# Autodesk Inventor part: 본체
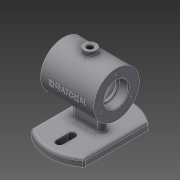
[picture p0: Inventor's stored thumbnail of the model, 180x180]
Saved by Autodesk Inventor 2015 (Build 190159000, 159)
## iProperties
Created: 2017-12
Part Number: 본체
Material: 일반
Document SubType Name: Modeling
Designer: SCD-A05
Density: 1 g/cm^3
Appearance: 기본값
Author: SCD-A05
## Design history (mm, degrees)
sketch "스케치1"
  geometry: L1 (-35, -42.426)-(-35, 42.426); L2 (35, 42.426)-(35, -42.426); A1 r 55 centre (0, 0) between (35, 42.426) and (-35, 42.426); A2 r 55 centre (0, 0) between (-35, -42.426) and (35, -42.426); 1 further point
  constraints: 4 end point, 4 point on circle, 2 centre point, 1 coincident, 1 parallel, 1 vertical
  dimensions: "d1" = 70 distance between parallel lines of L1 L2; "d2" = 35 distance from line of point (0, 0) L1; "d3" = 55 radius of A1; "d4" = 55 radius of A2
extrude "돌출1" new body sketch "스케치1" distance "d5" = 10; taper "d6" = 0 deg
sketch "스케치2"
  geometry: L1 (-15, -5)-(15, -5); L2 (15, 5)-(-15, 5); A1 r 55 centre (0, 0) between (-35, -42.426) and (35, -42.426) reference; A2 r 5 centre (-15, 0) between (-15, 5) and (-20, 0); A3 r 5 centre (-15, 0) between (-20, 0) and (-15, -5); A4 r 5 centre (15, 0) between (20, 0) and (15, 5); A5 r 5 centre (15, 0) between (15, -5) and (20, 0); 2 further points
  constraints: 8 point on circle, 4 centre point, 4 end point, 4 tangent, 2 concentric, 2 horizontal, 2 point on line, 1 parallel, 12 other
  dimensions: "d9" = 5 radius of A2; "d10" = 5 radius of A4; "d11" = 30 distance of A2.centre A4.centre; "d13" = 15 distance of A2.centre A1.centre; "d14" = 0 vertical distance of A1.centre A5.centre; "d15" = 10 distance between parallel lines of L2 L1
extrude "돌출2" join sketch "스케치2" distance "d16" = 52; taper "d17" = 0 deg
node "작업 평면1"
sketch "스케치5"
  geometry: L1 (-20, -10)-(-20, 0) reference; L2 (-20, 0)-(-5, 0) reference; L3 (-5, 0)-(-5, 52) reference; L4 (-5, 52)-(35, 52) reference; L5 (35, 52)-(35, 0) reference; L6 (35, 0)-(50, 0) reference; L7 (50, 0)-(50, -10) reference; L8 (50, -10)-(-20, -10) reference; L9 (-20, 82)-(50, 82); L10 (50, 82)-(50, 52); L11 (-20, 82)-(-20, 52); L12 (-20, 52)-(-5, 52); L13 (35, 52)-(50, 52); 1 further point
  constraints: 11 end point, 2 horizontal, 2 vertical, 1 collinear, 1 perpendicular
  dimensions: "d18" = 70 distance of L9.start L9.end; "d19" = 30 distance of L9.end L10.end; "d20" = 35 distance from line of point (15, -10) L11
revolve "회전1" sketch "스케치5" stored, may be unused: angle "d21" = 90 deg
sketch "스케치6"
  geometry: C1 r 30 at (0, 0) reference; C2 r 16 at (0, 0); 1 further point
  constraints: 1 centre point, 1 coincident
  dimensions: "d22" = 32 diameter of C2
extrude "돌출3" cut sketch "스케치6" distance "d23" = 12; taper "d24" = 0 deg
sketch "스케치7"
  geometry: C1 r 30 at (0, 0) reference; C2 r 16 at (0, 0); 1 further point
  constraints: 1 centre point, 1 coincident
  dimensions: "d25" = 32 diameter of C2
extrude "돌출4" cut sketch "스케치7" distance "d26" = 12; taper "d27" = 0 deg
node "작업 평면3"
sketch "스케치8"
  geometry: L1 (-52, -51.235)-(-62, -51.235) reference; L2 (-62, -51.235)-(-62, 51.235) reference; L3 (-62, 51.235)-(-52, 51.235) reference; L4 (-52, 51.235)-(-52, 0) reference; L5 (-52, 0)-(-52, -51.235) reference; L6 (-52, 0)-(-30, 0) reference; C1 r 25 at (0, 0); 2 further points
  constraints: 1 centre point, 1 coincident, 1 horizontal alignment
  dimensions: "d29" = 50 diameter of C1
extrude "돌출5" cut sketch "스케치8" distance "d30" = 40; taper "d31" = 0 deg
sketch "스케치9"
  geometry: C1 r 16 at (0, 0) reference; C2 r 14 at (0, 0); 1 further point
  constraints: 1 centre point, 1 coincident
  dimensions: "d32" = 28 diameter of C2
extrude "돌출6" cut sketch "스케치9" distance "d33" = 400; taper "d34" = 0 deg
sketch "스케치10"
  geometry: C1 r 16 at (0, 0) reference; 2 further points
  constraints: 1 horizontal alignment
  dimensions: "d35" = 23 distance of C1.centre point (-23, 0)
hole "구멍1" sketch "스케치10" at (-23, 0) diameter "d36" = 3.242; stored, may be unused: countersink angle "d40" = 90 deg, drill point angle "d42" = 118 deg; dims "d37" = 8, "d38" = 4, "d39" = 2, "d41" = 10
node "작업 평면4"
sketch "스케치11"
  geometry: L1 (15, -5)-(-15, -5) reference; L2 (-15, 5)-(15, 5) reference; L3 (35, 42.426)-(35, -42.426) reference; L4 (-35, -42.426)-(-35, 42.426) reference; L5 (-5, 24)-(-5, 24); L6 (5, 24)-(5, 40); L7 (-5, 40)-(-5, 40); L8 (-5, 40)-(-5, 24); L9 (-5, -40)-(-5, -24); L10 (5, -24)-(5, -40); A1 r 55 centre (0, 0) between (-35, -42.426) and (35, -42.426) reference; A2 r 5 centre (-15, 0) between (-15, 5) and (-15, -5) reference; A3 r 5 centre (15, 0) between (15, -5) and (15, 5) reference; A4 r 55 centre (0, 0) between (35, 42.426) and (-35, 42.426) reference; A5 r 55 centre (0, 0) between (-35, -42.426) and (35, -42.426) reference; A6 r 5 centre (0, 40) between (5, 40) and (-5, 40); A7 r 5 centre (0, 24) between (-5, 24) and (5, 24); A8 r 5 centre (0, -40) between (-5, -40) and (5, -40); A9 r 5 centre (0, -24) between (5, -24) and (-5, -24)
  constraints: 12 end point, 8 point on circle, 4 centre point, 4 vertical alignment, 2 parallel, 2 point on line, 2 vertical, 1 horizontal, 1 perpendicular, 1 tangent
  dimensions: "d46" = 10 distance of L6.end L7.end; "d49" = 16 distance of L7.end L5.start; "d55" = 24 distance of A1.centre A7.centre; "d56" = 5 radius of A7; "d60" = 5 radius of A8; "d61" = 10 diameter of A9; "d62" = 10 distance between parallel lines of L10 L9; "d63" = 24 distance of A1.centre A9.centre; "d64" = 16 distance of L9.start L9.end
extrude "돌출7" cut sketch "스케치11" distance "d65" = 400; taper "d66" = 0 deg
node "작업 평면5"
sketch "스케치12"
  geometry: L1 (-35, -30)-(-35, 30) reference; L2 (-35, 30)-(35, 30) reference; 2 further points
  constraints: 1 other
  dimensions: "d67" = 35 distance from line of L1 point (0, 0); "d68" = 30 distance from line of L2 point (0, 0)
feature "엠보싱1" sketch "스케치12" dims "d1" = 70, "d2" = 35, "d3" = 55, "d4" = 55, "d9" = 5, "d10" = 5, "d11" = 30, "d13" = 15, "d14" = 0, "d15" = 10, "d69" = 0.5, "d70" = 0
node "작업 평면6"
sketch "스케치13"
  geometry: C1 r 8 at (0, 0); 1 further point
  constraints: 1 centre point, 1 coincident
  dimensions: "d71" = 16 diameter of C1
extrude "돌출8" join sketch "스케치13" stored distance "d72" = 14; taper "d73" = 0 deg
sketch "스케치14"
  geometry: C1 r 8 at (0, 0) reference; C2 r 4 at (0, 0)
  constraints: 1 centre point, 1 coincident
  dimensions: "d74" = 8 diameter of C2
extrude "돌출9" cut sketch "스케치14" distance "d75" = 14; taper "d76" = 0 deg
sketch "스케치15"
  geometry: L1 (35, 78)-(23, 78) reference; L2 (23, 78)-(23, 76) reference; L3 (23, 76)-(20, 76) reference; L4 (20, 76)-(20, 87) reference; L5 (20, 87)-(8, 87) reference; L6 (8, 87)-(8, 85) reference; L7 (8, 85)-(4, 85) reference; L8 (4, 85)-(4, 99) reference; L9 (4, 99)-(8, 99) reference; L10 (8, 99)-(8, 92) reference; L11 (8, 92)-(35, 92) reference; L12 (35, 92)-(35, 86.621) reference; L13 (35, 86.621)-(25, 86.621) reference; L14 (25, 86.621)-(24.026, 85) reference; L15 (24.026, 85)-(25, 83.379) reference; L16 (25, 83.379)-(35, 83.379) reference; L17 (35, 83.379)-(35, 78) reference; L18 (-23, 78)-(-35, 78) reference; L19 (-35, 78)-(-35, 83.379) reference; L20 (-35, 83.379)-(-25, 83.379) reference; L21 (-25, 83.379)-(-24.026, 85) reference; L22 (-24.026, 85)-(-25, 86.621) reference; L23 (-25, 86.621)-(-35, 86.621) reference; L24 (-35, 86.621)-(-35, 92) reference; L25 (-35, 92)-(-8, 92) reference; L26 (-8, 92)-(-8, 99) reference; L27 (-8, 99)-(-4, 99) reference; L28 (-4, 99)-(-4, 85) reference; L29 (-4, 85)-(-8, 85) reference; L30 (-8, 85)-(-8, 87) reference; L31 (-8, 87)-(-20, 87) reference; L32 (-20, 87)-(-20, 76) reference; L33 (-20, 76)-(-23, 76) reference; L34 (-23, 76)-(-23, 78) reference; L35 (35, 10)-(35, 0) reference; L36 (35, 0)-(-35, 0) reference; L37 (-35, 0)-(-35, 10) reference; L38 (-35, 10)-(-20, 10) reference; L39 (-20, 10)-(-20, 32) reference; L40 (-20, 32)-(-35, 32) reference; L41 (-35, 32)-(-35, 46) reference; L42 (-35, 46)-(-23, 46) reference; L43 (-23, 46)-(-23, 48) reference; L44 (-23, 48)-(-20, 48) reference; L45 (-20, 48)-(-20, 37) reference; L46 (-20, 37)-(20, 37) reference; L47 (20, 37)-(20, 48) reference; L48 (20, 48)-(23, 48) reference; L49 (23, 48)-(23, 46) reference; L50 (23, 46)-(35, 46) reference; L51 (35, 46)-(35, 32) reference; L52 (35, 32)-(20, 32) reference; L53 (20, 32)-(20, 10) reference; L54 (20, 10)-(35, 10) reference; L55 (35, 78)-(35, 46) reference; L56 (-35, 46)-(-35, 78) reference; L57 (-35, 62)-(35, 62); L58 (-8, 87)-(8, 87); 1 further point
  constraints: 4 end point, 2 midpoint, 1 collinear
revolve "회전2" sketch "스케치15" stored, may be unused: angle "d77" = 90 deg
chamfer "모따기1" distance "d78" = 1; stored, may be unused: second distance "d79" = 2, angle "d80" = 45 deg
fillet "모깎기1" dims "d81" = 3
fillet "모깎기2" dims "d82" = 3
fillet "모깎기3" dims "d83" = 3
fillet "모깎기4" dims "d84" = 3
chamfer "모따기2" distance "d85" = 1; stored, may be unused: second distance "d86" = 2, angle "d87" = 45 deg
fillet "모깎기5" dims "d88" = 3
fillet "모깎기6" dims "d89" = 0.3
fillet "모깎기7" dims "d90" = 3
node "솔리드1"
pattern_circular "원형 패턴1" dims angle "d44" = 360 deg
mirror "대칭1"
node "절단 모서리 투영2"
node "절단 모서리 투영3"
node "절단 모서리 투영4"
node "절단 모서리 투영5"
other parameters: "d28" = -3
